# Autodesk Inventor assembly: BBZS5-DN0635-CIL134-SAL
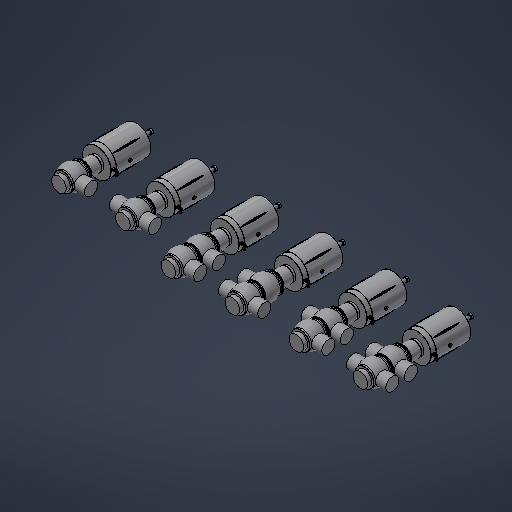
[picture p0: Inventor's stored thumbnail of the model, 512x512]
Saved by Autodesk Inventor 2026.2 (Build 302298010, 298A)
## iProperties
Created: 2009-10
Part Number: BBZS5-DN0635-CIL134-SAL
Document SubType Name: Assembly
Designer: marz-m
Title: \\BV-SRV1\Ufficio tecnico\cad3d\PNEUMATICA\Ing1-1\pne bbzp e derivate\BBZS5\BBZS5-DN0635-CIL134-SAL.iam.step
Sending System: Autodesk Inventor 2010
Preprocessor: Autodesk Inventor 2010
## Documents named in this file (7)
- C:\Users\marz-m\Downloads\pdf\2\BBZS5 3D STEP\BBZS5-DN0635-CIL134-SAL\BBZS5-DN0635-CIL134-SAL\BBZS5-DN0635-CIL134-SAL_TOP.iam
- C:\Users\marz-m\Downloads\pdf\2\BBZS5 3D STEP\BBZS5-DN0635-CIL134-SAL\BBZS5-DN0635-CIL134-SAL\Assemblaggio-DN065.ipt
- C:\Users\marz-m\Downloads\pdf\2\BBZS5 3D STEP\BBZS5-DN0635-CIL134-SAL\BBZS5-DN0635-CIL134-SAL\COR-INF-L-SAL-DN63.ipt
- C:\Users\marz-m\Downloads\pdf\2\BBZS5 3D STEP\BBZS5-DN0635-CIL134-SAL\BBZS5-DN0635-CIL134-SAL\COR-INF-T-SAL-DN63.ipt
- C:\Users\marz-m\Downloads\pdf\2\BBZS5 3D STEP\BBZS5-DN0635-CIL134-SAL\BBZS5-DN0635-CIL134-SAL\COR-SUP-L-SAL-DN63.ipt
- C:\Users\marz-m\Downloads\pdf\2\BBZS5 3D STEP\BBZS5-DN0635-CIL134-SAL\BBZS5-DN0635-CIL134-SAL\COR-SUP-T-SAL-DN63.ipt
- C:\Users\marz-m\Downloads\pdf\2\BBZS5 3D STEP\BBZS5-DN0635-CIL134-SAL\BBZS5-DN0635-CIL134-SAL\cil 134 tarabile.ipt
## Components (22 placed, 6 different names)
1. Assemblaggio-DN065:1
2. COR-INF-L-SAL-DN63.5:1
3. COR-INF-T-SAL-DN63.5:1
4. Assemblaggio-DN065:2
5. COR-INF-T-SAL-DN63.5:2
6. COR-INF-L-SAL-DN63.5:2
7. COR-SUP-L-SAL-DN63.5:1
8. Assemblaggio-DN065:3
9. COR-SUP-L-SAL-DN63.5:2
10. Assemblaggio-DN065:4
11. COR-INF-L-SAL-DN63.5:3
12. COR-SUP-T-SAL-DN63.5:1
13. Assemblaggio-DN065:5
14. COR-SUP-T-SAL-DN63.5:2
15. COR-INF-T-SAL-DN63.5:3
16. Assemblaggio-DN065:6
17. cil 134 tarabile:1
18. cil 134 tarabile:2
19. cil 134 tarabile:3
20. cil 134 tarabile:4
21. cil 134 tarabile:5
22. cil 134 tarabile:6
